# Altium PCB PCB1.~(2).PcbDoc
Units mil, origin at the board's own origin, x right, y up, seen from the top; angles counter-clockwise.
Board outline 6000 x 4000 mil, 2 copper layers (Top Layer, Bottom Layer); 3 components, 5 nets, 7 pads, 0 vias.
Unrouted connection lines stored in the file: 3.
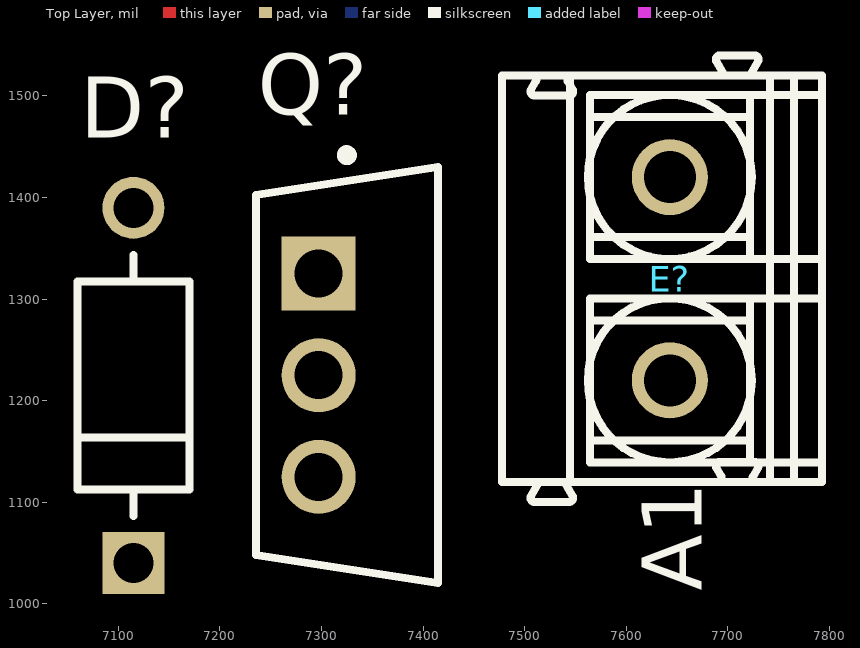
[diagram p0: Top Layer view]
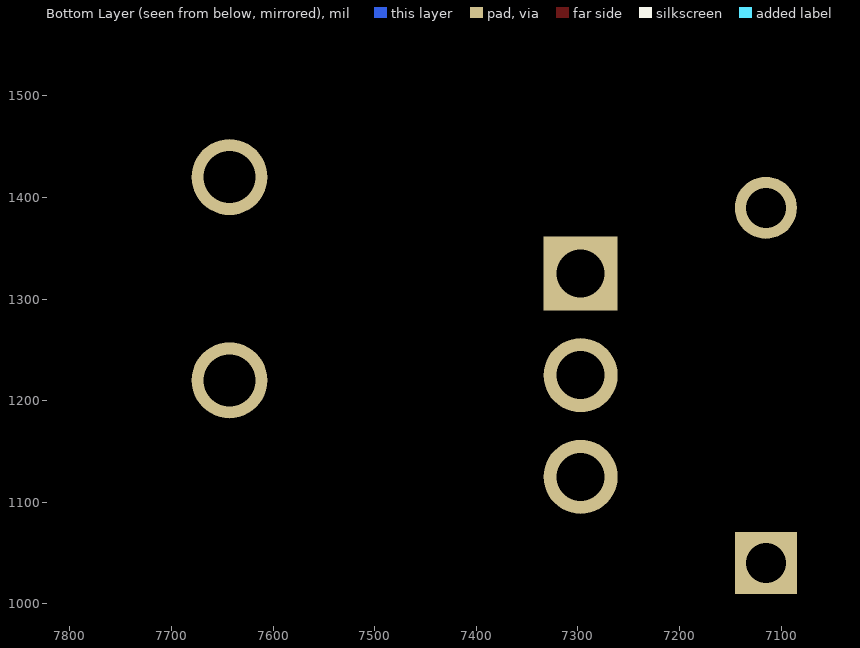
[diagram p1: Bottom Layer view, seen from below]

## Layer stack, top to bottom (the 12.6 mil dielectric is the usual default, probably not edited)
Top Solder: solder mask 0.4, Solder Resist, Dk 3.5
Top Layer: signal copper 1.4
Dielectric 1: dielectric 12.6, FR-4, Dk 4.8
Bottom Layer: signal copper 1.4
Bottom Solder: solder mask 0.4, Solder Resist, Dk 3.5

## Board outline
1000,1000 7000,1000 7000,5000 1000,5000

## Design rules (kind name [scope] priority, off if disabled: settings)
Clearance [All] p1: gap=10 ignorepadtopadclearanceinfootprint=FALSE
PolygonConnect [All] p1: connectstyle=Relief reliefconductorwidth=10 reliefentries=4 polygonreliefangle="90 Angle" airgapwidth=10
RoutingVias [All] p1: holewidth=28 width=50 viastyle="Through Hole" minholewidth=28 minwidth=50 maxholewidth=28 maxwidth=50
SolderMaskExpansion [All] p1: expansion=0 istentingtop=FALSE
SupplyNets "Schematic Supply Nets" [InNet('GND')] p1: voltage=0.000
Width [All] p1: maxlimit=10 minlimit=10 preferedwidth=10
30 further rules are at their usual default settings.

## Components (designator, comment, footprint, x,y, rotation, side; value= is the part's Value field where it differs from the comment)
D? "1N4007" FP-1N4007-MFG 7115,1215 r90 top value=15pF
E? "1760490000" PM_5_08_90_02 7635,1320 r90 top
Q? "IRLZ44NPbF" FP-PG-TO220-3-MFG 7325,1225 r0 top

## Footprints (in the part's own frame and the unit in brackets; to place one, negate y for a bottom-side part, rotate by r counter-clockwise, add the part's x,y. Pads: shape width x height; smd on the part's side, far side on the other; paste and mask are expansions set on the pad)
FP-1N4007-MFG [mm]
  rect 1.55x1.55 hole 1 paste-2539.97 mask+0: 1(-4.44,0)
  round 1.55 hole 1 paste-2539.97 mask+0: 2(4.44,0)
  silkscreen extent -3.26,-1.4 3.26,1.4, body extent -5.32,-1.5 5.32,1.5, height 0.25
FP-PG-TO220-3-MFG [mm]
  rect 1.85x1.85 hole 1.2 paste-2539.97 mask+0: 1(-0.705,2.54)
  round 1.85 hole 1.2 paste-2539.97 mask+0: 2(-0.705,0) 3(-0.705,-2.54)
  silkscreen extent -2.27,-5.2 2.27,5.62, body extent -2.37,-5.55 2.37,5.55, height 0.25
PM_5_08_90_02 [mm] "PM 5.08/02/90 3.5"
  round 1.9 hole 1.3: A1(-2.54,-0.2) A2(2.54,-0.2)
  silkscreen extent -5.58,-4 5.58,4, body extent -5.58,-4 5.58,4, height 10.01

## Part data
D?: library part CMP-123542-000001-1, "Rectifier diode 1000 V 1 A DO-41, ,", Capacitance=15pF, Forward Current=1A, Manufacturer=Diotec, Max Junction Temp=+175°C, Max Repetitive Reverse Voltage=1000V, Max Surge Forward Current=27A, Peak Reverse Current=5uA, Temperature="-50°C to +175°C", Temperature Range Low=-50°C
E?: library part CMP-1559-01627-1, "OMNIMATE Signal - series PM", Colour=Orange, Manufacturer=Weidmueller, Rated_current_use_group_B_UL_1059="15 A", Rated_voltage_for_surge_voltage_class_pollution_degree_II_2="600 V", Rated_voltage_use_group_B_UL_1059="300 V", UL_94_flammability_rating=V-0
Q?: library part CMP-32901-000488-1, "MOSFET N-CH 55V 47A TO220AB", Case/Package=TO-220, Continuous Drain Current (ID)=47A, Drain to Source Breakdown Voltage=55V, Drain to Source Resistance=35mR, Gate to Source Voltage (Vgs)=16V, Input Capacitance=1.7nF, Max Operating Temperature=175°C, Max Power Dissipation=110W, Min Operating Temperature=-55°C, Threshold Voltage=2V

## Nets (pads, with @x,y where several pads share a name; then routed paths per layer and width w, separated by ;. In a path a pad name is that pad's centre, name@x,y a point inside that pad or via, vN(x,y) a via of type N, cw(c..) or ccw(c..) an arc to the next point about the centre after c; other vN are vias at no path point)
GND: Q?.3
NetD?_1: D?.1 E?.A1 Q?.2
NetD?_2: D?.2 E?.A2
NetQ?_1: Q?.1
NetR?_1: 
